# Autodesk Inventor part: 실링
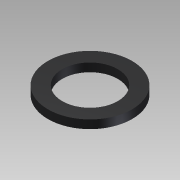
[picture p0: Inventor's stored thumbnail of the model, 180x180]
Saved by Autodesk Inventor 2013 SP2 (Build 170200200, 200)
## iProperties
Created: 2025-04
Part Number: 실링
Material: Generic
Document SubType Name: Modeling
Designer: i
Density: 1 g/cm^3
Author: i
변환 표준: STEP AP214IS
전처리기: Build: 200, Release: 2013 SP2 Update 6 - Date: Thu 07/17/2014
전송 단위: 밀리미터
불확실성: 0.01
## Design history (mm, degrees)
node "실링1"
node "솔리드1"
node "기준1"
